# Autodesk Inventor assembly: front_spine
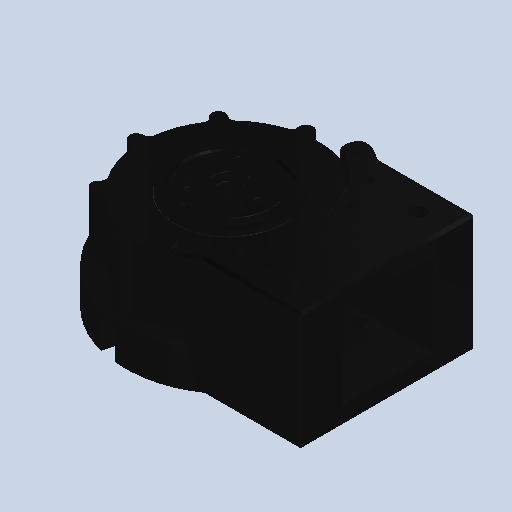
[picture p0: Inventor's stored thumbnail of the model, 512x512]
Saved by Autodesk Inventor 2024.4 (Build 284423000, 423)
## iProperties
Created: 2026-01
Part Number: front_spine
Document SubType Name: Assembly
Designer: AdminForWorker
Title: front_spine v1
Author: AdminForWorker
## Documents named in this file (4)
- c:\worker\convert-fusion-r06-cosv3\tmp\job-1\12\temp\files\56cf3632-e2c0-4c4a-8407-54084003577d\cdc6f789-ef5f-493d-ae9e-85c4a82fd71c.iam
- c:\worker\convert-fusion-r06-cosv3\tmp\job-1\12\temp\files\56cf3632-e2c0-4c4a-8407-54084003577d\CyberGear.ipt
- c:\worker\convert-fusion-r06-cosv3\tmp\job-1\12\temp\files\56cf3632-e2c0-4c4a-8407-54084003577d\body_split1.ipt
- c:\worker\convert-fusion-r06-cosv3\tmp\job-1\12\temp\files\56cf3632-e2c0-4c4a-8407-54084003577d\front_body.ipt
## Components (3 placed, 3 different names)
1. CyberGear:1
2. body_split1:1
3. front_body:1
